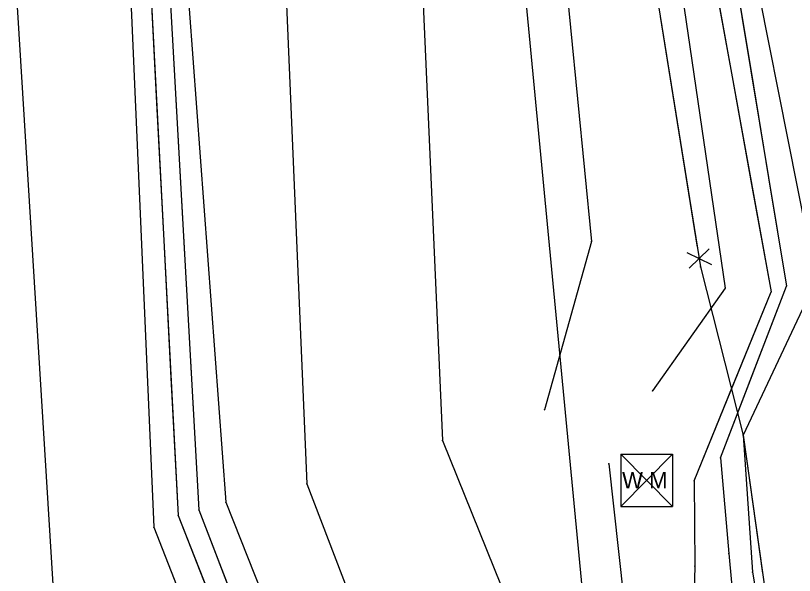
# Model space of a CAD drawing. Extents: x -99999 to 591807, y -99999 to 347168.
# Drawn here: x 588520.1 to 588661.3, y 345244.3 to 345345.8 of the extents above; entities that cross this region are included whole.
import ezdxf

# ---------------------------------------------------------------- set-up
doc = ezdxf.new("R2010")
doc.units = 0
for name, color, linetype in [('S_BREAKLINE', 7, 'Continuous'), ('S_DITCHLINE', 7, 'Continuous'), ('S_FENCE', 7, 'Continuous'), ('S_GRD_PT_SYM', 7, 'Continuous'), ('S_MSC_PT_SYM', 7, 'Continuous'), ('S_WATER_UTILITIES', 7, 'Continuous')]:
    doc.layers.add(name, color=color, linetype=linetype)

msp = doc.modelspace()

# ---------------------------------------------------------------- linework, layer by layer
at = {"layer": 'S_BREAKLINE'}
for points in [[(588619.23, 345373.44), (588592.06, 345380.23), (588566.45, 345378.55), (588551.47, 345380.83), (588548.22, 345382.6), (588542.86, 345379.88), (588521.05, 345378.26), (588520.08, 345352.32), (588527.17, 345236.77), (588553.48, 345184.56), (588583.07, 345115.62), (588613.24, 345076.61)], [(588645.08, 345382.49), (588640.99, 345378.55), (588638.07, 345369.09), (588648.69, 345296.36), (588635.53, 345277.72)], [(588645.08, 345382.49), (588648.42, 345381.11), (588649.83, 345374.72), (588665.14, 345297.65), (588651.98, 345269.68), (588653.66, 345244.85), (588663.81, 345185.3), (588669.22, 345148.47), (588646.72, 345142.69)], [(588592.06, 345380.23), (588593.48, 345358.85), (588597.44, 345268.74)], [(588566.45, 345378.55), (588568.85, 345356.35), (588572.86, 345260.85)], [(588551.84, 345377.15), (588550.87, 345356), (588558.17, 345257.51), (588580.62, 345200.97), (588606.6, 345151.17), (588636.21, 345092.69), (588648.17, 345077.76), (588656.26, 345062.88), (588660.79, 345052.64), (588646.16, 345037.87), (588629.12, 345025.15), (588622.59, 345013.75)], [(588545.01, 345375.49), (588540.7, 345354.17), (588545.11, 345252.99), (588567.42, 345195.93), (588590.63, 345135.27), (588622.03, 345081.29), (588635.76, 345068.69), (588644.89, 345057.38), (588636.34, 345048.49)], [(588619.23, 345373.44), (588618.15, 345369.53), (588624.45, 345304.8), (588615.98, 345274.31)], [(588597.44, 345268.74), (588616.07, 345222.61)], [(588627.62, 345264.49), (588632.09, 345223.93), (588638.04, 345192.35), (588646.72, 345142.69)], [(588572.86, 345260.85), (588592.19, 345210.42)]]:
    msp.add_lwpolyline(points, dxfattribs=at)
at = {"layer": 'S_DITCHLINE'}
for points in [[(588644.56, 345378.49), (588642.87, 345373.71), (588657.04, 345295.66)], [(588644.56, 345378.49), (588642.87, 345373.71), (588646.41, 345354.19), (588649.95, 345334.68), (588653.5, 345315.17), (588657.04, 345295.66)], [(588645.73, 345378.38), (588646.81, 345375.23), (588659.84, 345296.74)], [(588645.73, 345378.38), (588646.81, 345375.23), (588650.06, 345355.61), (588653.32, 345335.99), (588656.58, 345316.37), (588659.84, 345296.74)], [(588545.95, 345375.26), (588544.34, 345354.91), (588549.52, 345255.12), (588572.37, 345197.11), (588599.38, 345138.87), (588630.75, 345086.78)], [(588545.95, 345375.26), (588544.34, 345354.91), (588545.63, 345329.96), (588546.93, 345305.01), (588548.22, 345280.07), (588549.52, 345255.12), (588555.23, 345240.62), (588560.94, 345226.11), (588566.66, 345211.61), (588572.37, 345197.11), (588579.12, 345182.55), (588585.87, 345167.99), (588592.62, 345153.43), (588599.38, 345138.87), (588607.22, 345125.85), (588615.06, 345112.82), (588622.91, 345099.8), (588630.75, 345086.78)], [(588548.63, 345376.09), (588547.72, 345355.39), (588553.31, 345256.12), (588574.66, 345200.45), (588602.99, 345141.73), (588630.75, 345086.78), (588640.76, 345073.88), (588649.67, 345058.43), (588651.79, 345051.91), (588640.86, 345042.18), (588626.35, 345029.47), (588620.94, 345020.07), (588619.62, 345012.13)], [(588548.63, 345376.09), (588547.72, 345355.39), (588549.12, 345330.57), (588550.52, 345305.75), (588551.91, 345280.94), (588553.31, 345256.12), (588558.65, 345242.2), (588563.99, 345228.29), (588569.32, 345214.37), (588574.66, 345200.45), (588581.74, 345185.77), (588588.82, 345171.09), (588595.9, 345156.41), (588602.99, 345141.73), (588609.93, 345127.99), (588616.87, 345114.25), (588623.81, 345100.52), (588630.75, 345086.78), (588640.76, 345073.88), (588649.67, 345058.43)], [(588647.84, 345265.57), (588659.84, 345296.74)], [(588647.84, 345265.57), (588653.84, 345281.16), (588659.84, 345296.74)], [(588643.05, 345261.42), (588657.04, 345295.66)], [(588643.05, 345261.42), (588650.05, 345278.54), (588657.04, 345295.66)], [(588647.84, 345265.57), (588649.35, 345248.25), (588651.43, 345225.85), (588652.37, 345192.62), (588659.85, 345151.09)], [(588647.84, 345265.57), (588649.35, 345248.25), (588651.43, 345225.85), (588651.9, 345209.24), (588652.37, 345192.62), (588656.11, 345171.86), (588659.85, 345151.09)], [(588643.05, 345261.42), (588643.2, 345245.93), (588642.6, 345222.57), (588646.52, 345191.63), (588652.71, 345151.05)], [(588643.05, 345261.42), (588643.2, 345245.93), (588642.6, 345222.57), (588644.56, 345207.1), (588646.52, 345191.63), (588649.61, 345171.34), (588652.71, 345151.05)]]:
    msp.add_lwpolyline(points, dxfattribs=at)
at = {"layer": 'S_FENCE'}
for p, q in [((588632.93, 345370.69), (588644.21, 345300.21)), ((588645.77, 345303.45), (588642.18, 345299.97)), ((588641.72, 345302.8), (588646.22, 345300.61)), ((588644.21, 345300.21), (588651.98, 345269.68)), ((588651.98, 345269.68), (588663.81, 345185.3))]:
    msp.add_line(p, q, dxfattribs=at)
for points in [[(588636.94, 345345.61), (588643.64, 345303.8)], [(588644.21, 345300.21), (588651.98, 345269.68)], [(588651.98, 345269.68), (588655.49, 345244.65)]]:
    msp.add_lwpolyline(points, dxfattribs=at)
at = {"layer": 'S_GRD_PT_SYM'}
for points in [[(588624.45, 345304.8), (588624.5, 345304.79), (588624.45, 345304.8), (588624.47, 345304.85), (588624.45, 345304.8), (588624.4, 345304.82), (588624.45, 345304.8), (588624.44, 345304.76)], [(588648.69, 345296.36), (588648.73, 345296.33), (588648.69, 345296.36), (588648.72, 345296.4), (588648.69, 345296.36), (588648.65, 345296.39), (588648.69, 345296.36), (588648.66, 345296.32)], [(588659.84, 345296.74), (588659.89, 345296.75), (588659.84, 345296.74), (588659.83, 345296.79), (588659.84, 345296.74), (588659.79, 345296.74), (588659.84, 345296.74), (588659.85, 345296.69)], [(588659.84, 345296.74), (588659.79, 345296.76), (588659.84, 345296.74), (588659.82, 345296.7), (588659.84, 345296.74), (588659.88, 345296.73), (588659.84, 345296.74), (588659.86, 345296.79)], [(588657.04, 345295.66), (588657.09, 345295.67), (588657.04, 345295.66), (588657.03, 345295.71), (588657.04, 345295.66), (588656.99, 345295.65), (588657.04, 345295.66), (588657.05, 345295.61)], [(588657.04, 345295.66), (588656.99, 345295.68), (588657.04, 345295.66), (588657.02, 345295.61), (588657.04, 345295.66), (588657.09, 345295.64), (588657.04, 345295.66), (588657.06, 345295.7)], [(588635.53, 345277.72), (588635.57, 345277.69), (588635.53, 345277.72), (588635.56, 345277.76), (588635.53, 345277.72), (588635.49, 345277.74), (588635.53, 345277.72), (588635.5, 345277.68)], [(588615.98, 345274.31), (588616.02, 345274.29), (588615.98, 345274.31), (588615.99, 345274.35), (588615.98, 345274.31), (588615.93, 345274.32), (588615.98, 345274.31), (588615.96, 345274.26)], [(588651.98, 345269.68), (588652.03, 345269.68), (588651.98, 345269.68), (588651.98, 345269.73), (588651.98, 345269.68), (588651.93, 345269.67), (588651.98, 345269.68), (588651.98, 345269.63)], [(588597.44, 345268.74), (588597.49, 345268.74), (588597.44, 345268.74), (588597.44, 345268.79), (588597.44, 345268.74), (588597.39, 345268.74), (588597.44, 345268.74), (588597.44, 345268.69)], [(588597.44, 345268.74), (588597.49, 345268.76), (588597.44, 345268.74), (588597.42, 345268.79), (588597.44, 345268.74), (588597.39, 345268.72), (588597.44, 345268.74), (588597.46, 345268.69)], [(588647.84, 345265.57), (588647.89, 345265.58), (588647.84, 345265.57), (588647.84, 345265.62), (588647.84, 345265.57), (588647.79, 345265.57), (588647.84, 345265.57), (588647.85, 345265.52)], [(588647.84, 345265.57), (588647.8, 345265.59), (588647.84, 345265.57), (588647.83, 345265.52), (588647.84, 345265.57), (588647.89, 345265.55), (588647.84, 345265.57), (588647.86, 345265.62)], [(588627.62, 345264.49), (588627.62, 345264.54), (588627.62, 345264.49), (588627.57, 345264.49), (588627.62, 345264.49), (588627.62, 345264.44), (588627.62, 345264.49), (588627.67, 345264.49)], [(588627.62, 345264.49), (588627.67, 345264.49), (588627.62, 345264.49), (588627.62, 345264.54), (588627.62, 345264.49), (588627.57, 345264.48), (588627.62, 345264.49), (588627.63, 345264.44)], [(588572.86, 345260.85), (588572.91, 345260.85), (588572.86, 345260.85), (588572.86, 345260.9), (588572.86, 345260.85), (588572.81, 345260.85), (588572.86, 345260.85), (588572.86, 345260.8)], [(588572.86, 345260.85), (588572.91, 345260.87), (588572.86, 345260.85), (588572.84, 345260.9), (588572.86, 345260.85), (588572.81, 345260.83), (588572.86, 345260.85), (588572.88, 345260.8)], [(588643.05, 345261.42), (588643.1, 345261.42), (588643.05, 345261.42), (588643.05, 345261.47), (588643.05, 345261.42), (588643, 345261.42), (588643.05, 345261.42), (588643.05, 345261.37)], [(588643.05, 345261.42), (588643, 345261.44), (588643.05, 345261.42), (588643.03, 345261.37), (588643.05, 345261.42), (588643.1, 345261.4), (588643.05, 345261.42), (588643.07, 345261.47)], [(588558.17, 345257.51), (588558.22, 345257.53), (588558.17, 345257.51), (588558.15, 345257.56), (588558.17, 345257.51), (588558.13, 345257.49), (588558.17, 345257.51), (588558.19, 345257.46)], [(588549.52, 345255.12), (588549.56, 345255.14), (588549.52, 345255.12), (588549.5, 345255.17), (588549.52, 345255.12), (588549.47, 345255.1), (588549.52, 345255.12), (588549.53, 345255.07)], [(588553.31, 345256.12), (588553.36, 345256.14), (588553.31, 345256.12), (588553.29, 345256.17), (588553.31, 345256.12), (588553.27, 345256.1), (588553.31, 345256.12), (588553.33, 345256.07)], [(588545.11, 345252.99), (588545.16, 345253.01), (588545.11, 345252.99), (588545.1, 345253.03), (588545.11, 345252.99), (588545.07, 345252.97), (588545.11, 345252.99), (588545.13, 345252.94)], [(588649.35, 345248.25), (588649.4, 345248.25), (588649.35, 345248.25), (588649.35, 345248.3), (588649.35, 345248.25), (588649.3, 345248.24), (588649.35, 345248.25), (588649.36, 345248.2)], [(588643.2, 345245.93), (588643.25, 345245.93), (588643.2, 345245.93), (588643.2, 345245.98), (588643.2, 345245.93), (588643.15, 345245.93), (588643.2, 345245.93), (588643.2, 345245.88)], [(588653.66, 345244.85), (588653.71, 345244.86), (588653.66, 345244.85), (588653.65, 345244.9), (588653.66, 345244.85), (588653.61, 345244.85), (588653.66, 345244.85), (588653.67, 345244.8)]]:
    msp.add_lwpolyline(points, close=True, dxfattribs=at)
at = {"layer": 'S_MSC_PT_SYM'}
for points in [[(588644.21, 345300.21), (588644.21, 345300.26), (588644.21, 345300.21), (588644.16, 345300.21), (588644.21, 345300.21), (588644.21, 345300.16), (588644.21, 345300.21), (588644.26, 345300.21)], [(588651.98, 345269.68), (588651.98, 345269.73), (588651.98, 345269.68), (588651.93, 345269.68), (588651.98, 345269.68), (588651.98, 345269.63), (588651.98, 345269.68), (588652.03, 345269.68)]]:
    msp.add_lwpolyline(points, dxfattribs=at)
at = {"layer": 'S_WATER_UTILITIES'}
for p, q in [((588607.92, 345397.15), (588630.8, 345157.55)), ((588629.8, 345266.26), (588639.14, 345266.26)), ((588629.8, 345266.26), (588629.8, 345256.76)), ((588629.8, 345266.26), (588639.14, 345256.76)), ((588639.14, 345266.26), (588629.8, 345256.76)), ((588639.14, 345266.26), (588639.14, 345256.76)), ((588629.8, 345256.76), (588639.14, 345256.76))]:
    msp.add_line(p, q, dxfattribs=at)

# ---------------------------------------------------------------- texts
msp.add_text('W M', height=3, rotation=360, dxfattribs=at).set_placement((588630.01, 345260.02))

doc.saveas('drawing.dxf')
